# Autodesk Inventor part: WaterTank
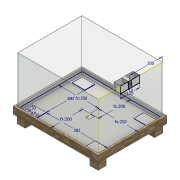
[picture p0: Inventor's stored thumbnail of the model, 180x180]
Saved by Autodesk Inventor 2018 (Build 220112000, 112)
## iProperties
Created: 2018-05
Part Number: WaterTank
Material: Generic
Document SubType Name: Modeling
Designer: arivu
Density: 1 g/cm^3
Appearance: Default
Author: arivu
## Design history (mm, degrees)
workplane "Work Plane2"
workplane "Work Plane4"
sketch "Sketch1"
  geometry: L1 (-250, 200)-(250, 200); L2 (250, 200)-(250, -200); L3 (250, -200)-(-250, -200); L4 (-250, -200)-(-250, 200); 1 further point
  constraints: 8 end point, 2 parallel, 1 horizontal, 1 perpendicular
  dimensions: "d0" = 250 distance from line of point (0, 0) L4 (= 0.5 x width); "d1" = 250 distance from line of L2 point (0, 0) (= d0); "d2" = 200 distance from line of L3 point (0, 0) (= 0.5 x height); "d3" = 200 distance from line of L1 point (0, 0) (= d2)
extrude "Extrusion1" new body sketch "Sketch1" distance "d4" = 300 (= depth); taper "d5" = 0 deg
sketch "Sketch2"
  geometry: L1 (-250, 200)-(250, 200) reference; L2 (250, -200)-(-250, -200); L3 (-250, -200)-(-250, 200); L4 (-250, 200)-(250, 200); L5 (250, 200)-(250, -200); L6 (262, -212)-(-262, -212); L7 (-262, -212)-(-262, 212); L8 (-262, 212)-(262, 212); L9 (262, 212)-(262, -212); 1 further point
  constraints: 16 end point, 4 parallel, 2 horizontal, 2 perpendicular
  dimensions: "d19" = 12 distance between parallel lines of L5 L9 (computed from osb); "d20" = 12 distance between parallel lines of L2 L6 (computed from osb); "d21" = 12 distance between parallel lines of L7 L3 (computed from osb); "d22" = 12 distance between parallel lines of L8 L1 (computed from osb)
extrude "Extrusion2" new body sketch "Sketch2" distance "d7" = 11 (= osb); taper "d8" = 0 deg
sketch "Sketch3"
  geometry: L1 (250, -200)-(-250, -200) reference; L2 (250, -200)-(200, -200); L3 (200, -200)-(200, -150); L4 (200, -150)-(250, -150); L5 (250, -150)-(250, -200); L6 (-250, 200)-(250, 200) reference; L7 (250, 200)-(200, 200); L8 (200, 200)-(200, 150); L9 (200, 150)-(250, 150); L10 (250, 150)-(250, 200); L11 (-250, 200)-(-200, 200); L12 (-200, 200)-(-200, 150); L13 (-200, 150)-(-250, 150); L14 (-250, 150)-(-250, 200); L15 (-250, -200)-(-200, -200); L16 (-200, -200)-(-200, -150); L17 (-200, -150)-(-250, -150); L18 (-250, -150)-(-250, -200); 1 further point
  constraints: 32 end point, 8 parallel, 4 horizontal, 4 perpendicular
  dimensions: "d9" = 50 distance of L3.end L4.end (= legs); "d10" = 50 distance of L2.end L3.end (= d9); "d11" = 50 distance of L9.end L8.end (= d9); "d12" = 50 distance of L8.end L7.end (= d9); "d13" = 50 distance of L12.end L13.end (= d9); "d14" = 50 distance of L11.end L12.end (= d9); "d15" = 50 distance of L17.end L16.end (= d9); "d16" = 50 distance of L16.end L15.end (= d9)
extrude "Extrusion3" new body sketch "Sketch3" distance "d17" = 50 (= leg_lenght); taper "d18" = 0 deg
sketch "Sketch4"
  geometry: L1 (-262, -212)-(-262, 212) reference; L2 (262, -212)-(-262, -212) reference; L3 (-262, 212)-(262, 212); L4 (262, 212)-(262, -212); L5 (262, -212)-(-262, -212); L6 (-262, -212)-(-262, 212); L7 (-251, 201)-(251, 201); L8 (251, 201)-(251, -201); L9 (251, -201)-(-251, -201); L10 (-251, -201)-(-251, 201); 1 further point
  constraints: 16 end point, 4 parallel, 2 horizontal, 2 perpendicular
  dimensions: "d23" = 11 distance between parallel lines of L7 L3 (= osb); "d25" = 11 distance between parallel lines of L10 L1 (= osb); "d26" = 11 distance between parallel lines of L2 L9 (= osb); "d27" = 11 distance between parallel lines of L4 L8 (= osb)
extrude "Extrusion4" new body sketch "Sketch4" distance "d28" = 33 (= 3 x osb); taper "d29" = 0 deg
sketch "Sketch5"
  geometry: L1 (-200, 150)-(-250, 150) reference; L2 (-10.7, 8.025)-(-200, 150); L3 (250, 150)-(200, 150) reference; L4 (10.7, 8.025)-(200, 150); L5 (-250, -150)-(-200, -150) reference; L6 (-10.7, -8.025)-(-200, -150); L7 (200, -200)-(200, -150) reference; L8 (10.7, -8.025)-(200, -150); L9 (0, 0)-(10.7, 0); L10 (0, 0)-(-10.7, 0); L11 (0, 0)-(0, 17.3); L12 (0, 0)-(0, -17.3); L13 (-10.7, 0)-(-10.7, 17.3); L14 (-10.7, 17.3)-(0, 17.3); L15 (0, 17.3)-(10.7, 17.3); L16 (10.7, 17.3)-(10.7, 0); L17 (10.7, -17.3)-(0, -17.3); L18 (10.7, 0)-(10.7, -17.3); L19 (0, -17.3)-(-10.7, -17.3); L20 (-10.7, -17.3)-(-10.7, 0); L21 (-200, 150)-(-182, 150); L22 (-200, 150)-(-200, -150); L23 (-200, 200)-(-200, 150) reference; L24 (-200, -150)-(200, -150); C1 r 2.5 at (-200, 150); C2 r 2.5 at (-182, 150); C3 r 2.5 at (-200, -150); C4 r 2.5 at (-182, -150); C5 r 2.5 at (182, 150); C6 r 2.5 at (200, 150); C7 r 2.5 at (182, -150); C8 r 2.5 at (200, -150)
  constraints: 38 end point, 8 centre point, 7 point on line, 5 horizontal, 5 perpendicular, 4 vertical, 2 coincident, 1 collinear, 12 other
  dimensions: "d30" = 10.7 distance of L9.start L9.end; "d31" = 10.7 distance of L9.start L10.end; "d32" = 17.3 distance of L9.start L11.end; "d33" = 17.3 distance of L9.start L12.end; "d34" = 5 diameter of C1; "d35" = 18 distance of L21.start L21.end; "d36" = 5 diameter of C2; "d39" = 300 distance of L21.start C3.centre; "d42" = 382 distance of L21.start C5.centre
extrude "Extrusion5" cut sketch "Sketch5" distance "d45" = 1.6; taper "d46" = 0 deg
extrude "Extrusion6" cut sketch "Sketch5" distance "d47" = 1; taper "d48" = 0 deg
workplane "Work Plane1"
workplane "Work Plane3"
sketch "Sketch6"
  geometry: L1 (-497, 347)-(-497, 397) reference; L2 (3, 47)-(3, -3) reference; L3 (-497, 397)-(3, 397); L4 (3, 397)-(3, -3); L5 (3, -3)-(-497, -3); L6 (-497, -3)-(-497, 397); 1 further point
  constraints: 8 end point, 2 parallel, 1 horizontal, 1 perpendicular
extrude "Extrusion7" new body sketch "Sketch6" distance "d49" = 11 (= osb); taper "d50" = 0 deg
sketch "Sketch7"
  geometry: L1 (477, 17)-(399, 17); L2 (399, 17)-(399, 77); L3 (399, 77)-(477, 77); L4 (477, 77)-(477, 17); L5 (447, 47)-(47, 47) reference; L6 (447, 347)-(447, 47) reference; L7 (399, 377)-(477, 377); L8 (477, 377)-(477, 317); L9 (477, 317)-(399, 317); L10 (399, 317)-(399, 377); L11 (17, 77)-(95, 77); L12 (95, 77)-(95, 17); L13 (95, 17)-(17, 17); L14 (17, 17)-(17, 77); L15 (17, 377)-(95, 377); L16 (95, 377)-(95, 317); L17 (95, 317)-(17, 317); L18 (17, 317)-(17, 377); 3 further points
  constraints: 32 end point, 2 horizontal, 2 parallel, 1 perpendicular, 1 vertical, 24 other
  dimensions: "d53" = 30 distance from line of point (447, 47) L4; "d54" = 30 distance from line of L2 point (429, 47); "d55" = 30 distance from line of L3 point (447, 47); "d56" = 30 distance from line of L1 point (429, 47); "d59" = 300 distance of L2.end L7.start; "d62" = 382 distance of L2.end L11.start
extrude "Extrusion8" cut sketch "Sketch7" distance "d65" = 1.5; taper "d66" = 0 deg
sketch "Sketch8"
  geometry: L1 (477, 17)-(399, 17) reference; L2 (477, 77)-(477, 17) reference; L3 (399, 77)-(477, 77) reference; L4 (399, 17)-(399, 77) reference; 1 further point
extrude "Extrusion9" new body sketch "Sketch8" distance "d67" = 1.5; taper "d68" = 0 deg
pattern_linear "Rectangular Pattern1" dims "d71" = 382, "d74" = 300
shell "Shell1" dims "d6" = 3
sketch "Sketch9"
  geometry: 1 further point
sketch "Sketch10"
  geometry: L1 (0, 0)-(297, 0) reference; L2 (297, 197)-(297, 237); L3 (255.836, 237)-(255.836, 157); L4 (297, 197)-(297, 157); L5 (255.836, 237)-(255.836, 257); L6 (255.836, 257)-(297, 257); L7 (297, 257)-(297, 237); L8 (255.836, 157)-(255.836, 137); L9 (255.836, 137)-(297, 137); L10 (297, 137)-(297, 157); L11 (255.836, 197)-(297, 197); L12 (297, 197)-(297, 187); L13 (297, 187)-(255.836, 187); L14 (255.836, 187)-(255.836, 197); L15 (255.836, 197)-(255.836, 207); L16 (255.836, 207)-(297, 207); L17 (297, 197)-(297, 207); 4 further points; 2 other entities
  constraints: 32 end point, 5 perpendicular, 3 point on line, 2 vertical, 1 collinear, 1 horizontal, 1 midpoint, 6 other
  dimensions: "d90" = 200 distance of point (297, 397) L2.start; "d93" = 120 distance of L8.end L5.end; "d94" = 10 distance of L2.start L12.end; "d95" = 10 distance of L11.start L15.end
extrude "Extrusion12" new body sketch "Sketch10" distance "d96" = 40; taper "d97" = 0 deg
extrude "Extrusion13" new body sketch "Sketch10" distance "d98" = 40; taper "d99" = 0 deg
sketch "Sketch13"
  geometry: L1 (-40, 0)-(-25, 0); L2 (-25, 0)-(-40, 41.164); L3 (0, 41.164)-(-494, 41.164) reference; L4 (-40, 41.164)-(-40, 0); 1 further point
  constraints: 6 end point, 1 point on line
  dimensions: "d100" = 15 distance of L1.start L1.end
extrude "Extrusion14" cut sketch "Sketch13" stored distance "d101" = 40; taper "d102" = 0 deg
shell "Shell4" dims "d103" = 1
fillet "Fillet3" dims "d105" = 4
body "Solid1"
body "Solid2"
body "Solid3"
body "Solid4"
body "Solid5"
body "Solid6"
body "Solid8"
body "Solid9"
other parameters: "depth" = 300 [user parameter; used in 1 equation term], "osb" = 11 [user parameter; used in 11 equation terms], "legs" = 50 [user parameter; used in 1 equation term], "leg_lenght" = 50 [user parameter; used in 1 equation term], "d76" = 22, "d77" = 7.8, "d78" = 18.8
